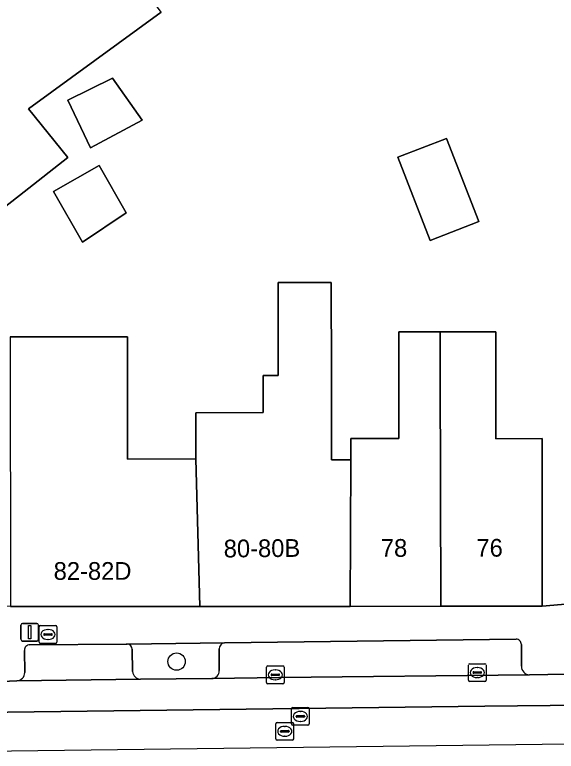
# Model space of a CAD drawing. Extents: x 159716 to 160783, y 383290 to 384031.
# Drawn here: x 159999.48 to 160030, y 383289.88 to 383331.4 of the extents above; entities that cross this region are included whole.
import ezdxf

# ---------------------------------------------------------------- set-up
doc = ezdxf.new("R2010")
doc.units = 0
for name, color, linetype in [('IMGEO_Boom', 7, 'Continuous'), ('IMGEO_Brandkraan', 7, 'Continuous'), ('IMGEO_Erf', 7, 'Continuous'), ('IMGEO_Groenvoorziening', 7, 'Continuous'), ('IMGEO_Kolk', 7, 'Continuous'), ('IMGEO_Lichtmast', 7, 'Continuous'), ('IMGEO_Pand', 7, 'Continuous'), ('IMGEO_Pand_nummerreeks', 7, 'Continuous'), ('IMGEO_Parkeervlak_open', 7, 'Continuous'), ('IMGEO_Rijbaan_lokaal_gesloten', 7, 'Continuous'), ('IMGEO_Rijbaan_lokaal_open', 7, 'Continuous'), ('IMGEO_Rioolput', 7, 'Continuous'), ('IMGEO_Voetpad_open', 7, 'Continuous')]:
    doc.layers.add(name, color=color, linetype=linetype)

msp = doc.modelspace()

# ---------------------------------------------------------------- linework, layer by layer
at = {"layer": 'IMGEO_Boom'}
msp.add_circle((160008.6, 383294.941), 0.489, dxfattribs=at)
at = {"layer": 'IMGEO_Brandkraan'}
for p, q in [((160000.852, 383296.043), (160000.852, 383296.895)), ((160000.927, 383296.969), (160001.779, 383296.969)), ((160001.34, 383296.749), (160001.365, 383296.749)), ((160001.853, 383296.895), (160001.853, 383296.043)), ((160001.111, 383296.463), (160001.111, 383296.475)), ((160001.549, 383296.426), (160001.151, 383296.426)), ((160001.154, 383296.512), (160001.552, 383296.512)), ((160001.595, 383296.475), (160001.595, 383296.463)), ((160001.779, 383295.969), (160000.927, 383295.969)), ((160001.363, 383296.189), (160001.338, 383296.189))]:
    msp.add_line(p, q, dxfattribs=at)
for points in [[(160000.852, 383296.043), (160000.852, 383296.895)], [(160000.927, 383296.969), (160001.779, 383296.969)], [(160001.853, 383296.895), (160001.853, 383296.043)], [(160001.779, 383295.969), (160000.927, 383295.969)]]:
    msp.add_lwpolyline(points, dxfattribs=at)
for centre, radius, start, end in [((160000.929, 383296.893), 0.0765, 91.552, 178.448), ((160000.929, 383296.893), 0.0765, 91.552, 178.448), ((160001.777, 383296.893), 0.0765, 1.552, 88.448), ((160001.777, 383296.893), 0.0765, 1.552, 88.448), ((160001.151, 383296.472), 0.0403, 85.8775, 175.7526), ((160001.148, 383296.462), 0.0366, 178.938, 274.7102), ((160001.552, 383296.469), 0.043, 264.8664, 352.4533), ((160001.556, 383296.474), 0.0386, 1.7309, 96.639), ((160000.929, 383296.045), 0.0765, 181.552, 268.448), ((160000.929, 383296.045), 0.0765, 181.552, 268.448), ((160001.777, 383296.045), 0.0765, 271.552, 358.448), ((160001.777, 383296.045), 0.0765, 271.552, 358.448)]:
    msp.add_arc(centre, radius, start, end, dxfattribs=at)
for centre, major_axis, ratio, start_param, end_param in [((160001.339, 383296.469), (-0.387, 0.002), 0.722429, 4.712389, 7.853982), ((160001.364, 383296.469), (-0.39, 0.002), 0.717154, 1.570796, 4.712389)]:
    msp.add_ellipse(centre, major_axis=major_axis, ratio=ratio, start_param=start_param, end_param=end_param, dxfattribs=at)
at = {"layer": 'IMGEO_Erf'}
for points in [[(160007.736, 383331.548), (160000.251, 383326.099), (160002.477, 383323.348), (160000, 383321.412), (159989.169, 383312.946), (159985.228, 383309.868), (159986.866, 383307.586)], [(159999.223, 383313.243), (160005.829, 383313.244), (160005.837, 383306.359), (160009.683, 383306.364), (160009.68, 383308.972), (160013.483, 383308.976), (160013.48, 383311.06), (160014.323, 383311.061), (160014.317, 383316.311), (160017.318, 383316.315), (160017.325, 383311.064), (160017.331, 383306.308), (160018.412, 383306.309), (160018.411, 383307.51), (160021.128, 383307.514), (160021.124, 383311.387), (160021.122, 383313.526), (160023.458, 383313.529), (160026.586, 383313.532), (160026.588, 383311.394), (160026.593, 383307.503), (160029.195, 383307.507), (160029.205, 383298.058), (160051.807, 383300.026)]]:
    msp.add_lwpolyline(points, dxfattribs=at)
for points in [[(160006.667, 383325.468), (160003.756, 383323.899), (160002.463, 383326.581), (160004.981, 383327.826)], [(160025.64, 383319.74), (160022.893, 383318.672), (160021.068, 383323.366), (160023.815, 383324.434)], [(160005.754, 383320.23), (160003.297, 383318.582), (160001.665, 383321.437), (160004.228, 383322.901)]]:
    msp.add_lwpolyline(points, close=True, dxfattribs=at)
at = {"layer": 'IMGEO_Groenvoorziening'}
for points in [[(160011.293, 383295.996), (160005.822, 383295.928)], [(160006.089, 383295.635), (160006.118, 383294.381)], [(160011.004, 383294.436), (160011.007, 383295.654)], [(160006.567, 383293.953), (160010.577, 383293.982)]]:
    msp.add_lwpolyline(points, dxfattribs=at)
for centre, radius, start, end in [((160005.798, 383295.638), 0.291, 359.4128, 85.2707), ((160011.345, 383295.662), 0.339, 98.9183, 181.2731), ((160006.571, 383294.406), 0.453, 183.1957, 269.5477), ((160010.558, 383294.427), 0.446, 272.4144, 1.0963)]:
    msp.add_arc(centre, radius, start, end, dxfattribs=at)
at = {"layer": 'IMGEO_Kolk'}
for p, q in [((160013.737, 383294.692), (160014.589, 383294.692)), ((160025.044, 383293.896), (160025.044, 383294.748)), ((160025.119, 383294.822), (160025.971, 383294.822)), ((160026.045, 383294.748), (160026.045, 383293.896)), ((160013.662, 383293.766), (160013.662, 383294.618)), ((160013.964, 383294.235), (160014.362, 383294.235)), ((160014.15, 383294.472), (160014.175, 383294.472)), ((160014.663, 383294.618), (160014.663, 383293.766)), ((160025.303, 383294.316), (160025.303, 383294.328)), ((160025.741, 383294.279), (160025.343, 383294.279)), ((160025.346, 383294.365), (160025.744, 383294.365)), ((160025.532, 383294.602), (160025.557, 383294.602)), ((160025.787, 383294.328), (160025.787, 383294.316)), ((160013.921, 383294.186), (160013.921, 383294.198)), ((160014.359, 383294.149), (160013.961, 383294.149)), ((160014.173, 383293.912), (160014.148, 383293.912)), ((160014.405, 383294.198), (160014.405, 383294.186)), ((160025.971, 383293.822), (160025.119, 383293.822)), ((160025.555, 383294.042), (160025.53, 383294.042)), ((160014.589, 383293.692), (160013.737, 383293.692))]:
    msp.add_line(p, q, dxfattribs=at)
for points in [[(160013.737, 383294.692), (160014.589, 383294.692)], [(160025.044, 383293.896), (160025.044, 383294.748)], [(160025.119, 383294.822), (160025.971, 383294.822)], [(160026.045, 383294.748), (160026.045, 383293.896)], [(160013.662, 383293.766), (160013.662, 383294.618)], [(160014.663, 383294.618), (160014.663, 383293.766)], [(160025.971, 383293.822), (160025.119, 383293.822)], [(160014.589, 383293.692), (160013.737, 383293.692)]]:
    msp.add_lwpolyline(points, dxfattribs=at)
for centre, radius, start, end in [((160013.739, 383294.616), 0.0765, 91.552, 178.448), ((160013.739, 383294.616), 0.0765, 91.552, 178.448), ((160014.587, 383294.616), 0.0765, 1.552, 88.448), ((160014.587, 383294.616), 0.0765, 1.552, 88.448), ((160025.121, 383294.746), 0.0765, 91.552, 178.448), ((160025.121, 383294.746), 0.0765, 91.552, 178.448), ((160025.969, 383294.746), 0.0765, 1.552, 88.448), ((160025.969, 383294.746), 0.0765, 1.552, 88.448), ((160013.961, 383294.195), 0.0403, 85.8775, 175.7526), ((160014.366, 383294.197), 0.0386, 1.7309, 96.639), ((160025.343, 383294.325), 0.0403, 85.8775, 175.7526), ((160025.34, 383294.315), 0.0366, 178.938, 274.7102), ((160025.744, 383294.322), 0.043, 264.8664, 352.4533), ((160025.748, 383294.327), 0.0386, 1.7309, 96.639), ((160013.958, 383294.185), 0.0366, 178.938, 274.7102), ((160014.362, 383294.192), 0.043, 264.8664, 352.4533), ((160025.121, 383293.898), 0.0765, 181.552, 268.448), ((160025.121, 383293.898), 0.0765, 181.552, 268.448), ((160025.969, 383293.898), 0.0765, 271.552, 358.448), ((160025.969, 383293.898), 0.0765, 271.552, 358.448), ((160013.739, 383293.768), 0.0765, 181.552, 268.448), ((160013.739, 383293.768), 0.0765, 181.552, 268.448), ((160014.587, 383293.768), 0.0765, 271.552, 358.448), ((160014.587, 383293.768), 0.0765, 271.552, 358.448)]:
    msp.add_arc(centre, radius, start, end, dxfattribs=at)
for centre, major_axis, ratio, start_param, end_param in [((160014.149, 383294.192), (-0.387, 0.002), 0.722429, 4.712389, 7.853982), ((160014.174, 383294.192), (-0.39, 0.002), 0.717154, 1.570796, 4.712389), ((160025.531, 383294.322), (-0.387, 0.002), 0.722429, 4.712389, 7.853982), ((160025.556, 383294.322), (-0.39, 0.002), 0.717154, 1.570796, 4.712389)]:
    msp.add_ellipse(centre, major_axis=major_axis, ratio=ratio, start_param=start_param, end_param=end_param, dxfattribs=at)
at = {"layer": 'IMGEO_Lichtmast'}
for p, q in [((159999.823, 383296.196), (159999.823, 383296.996)), ((159999.823, 383296.996), (159999.823, 383296.196)), ((159999.923, 383297.096), (160000.713, 383297.096)), ((160000.713, 383297.096), (159999.923, 383297.096)), ((160000.813, 383296.996), (160000.813, 383296.196)), ((160000.813, 383296.196), (160000.813, 383296.996)), ((160000.713, 383296.096), (159999.923, 383296.096)), ((159999.923, 383296.096), (160000.713, 383296.096))]:
    msp.add_line(p, q, dxfattribs=at)
msp.add_lwpolyline([(160000.243, 383296.971), (160000.393, 383296.971), (160000.393, 383296.221), (160000.243, 383296.221), (160000.243, 383296.971)], dxfattribs=at)
for centre, start, end in [((159999.923, 383296.996), 90, 180), ((159999.923, 383296.996), 90, 180), ((160000.713, 383296.996), 0, 90), ((160000.713, 383296.996), 360, 90), ((159999.923, 383296.196), 180, 270), ((159999.923, 383296.196), 180, 270), ((160000.713, 383296.196), 270, 0), ((160000.713, 383296.196), 270, 0)]:
    msp.add_arc(centre, 0.1, start, end, dxfattribs=at)
at = {"layer": 'IMGEO_Pand'}
for points in [[(160000, 383321.412), (160002.477, 383323.348), (160000.251, 383326.099), (160007.736, 383331.548), (160002.683, 383338.49), (159994.989, 383332.888), (159993.871, 383331.942), (159980.078, 383320.999), (159985.228, 383309.868), (159989.169, 383312.946)], [(160002.463, 383326.581), (160003.756, 383323.899), (160006.667, 383325.468), (160004.981, 383327.826)], [(160025.64, 383319.74), (160023.815, 383324.434), (160021.068, 383323.366), (160022.893, 383318.672)], [(160004.228, 383322.901), (160001.665, 383321.437), (160003.297, 383318.582), (160005.754, 383320.23)], [(160018.39, 383298.054), (160018.412, 383306.309), (160017.331, 383306.308), (160017.325, 383311.064), (160017.318, 383316.315), (160014.317, 383316.311), (160014.323, 383311.061), (160013.48, 383311.06), (160013.483, 383308.976), (160009.68, 383308.972), (160009.683, 383306.364), (160009.914, 383298.051)], [(160018.39, 383298.054), (160023.487, 383298.056), (160023.461, 383311.39), (160023.458, 383313.529), (160021.122, 383313.526), (160021.124, 383311.387), (160021.128, 383307.514), (160018.411, 383307.51), (160018.412, 383306.309)], [(160023.458, 383313.529), (160023.461, 383311.39), (160023.487, 383298.056), (160029.205, 383298.058), (160029.195, 383307.507), (160026.593, 383307.503), (160026.588, 383311.394), (160026.586, 383313.532)], [(160009.683, 383306.364), (160005.837, 383306.359), (160005.829, 383313.244), (159999.223, 383313.243), (159999.241, 383298.046), (160000, 383298.047), (160009.914, 383298.051)]]:
    msp.add_lwpolyline(points, close=True, dxfattribs=at)
at = {"layer": 'IMGEO_Parkeervlak_open'}
for points in [[(160005.822, 383295.928), (160005.765, 383295.928), (160000.325, 383295.889)], [(160027.732, 383296.209), (160011.293, 383295.996)], [(160028.033, 383294.681), (160028.029, 383295.897)], [(160000.031, 383295.57), (160000.04, 383294.322)], [(160006.118, 383294.381), (160006.089, 383295.635)], [(160011.007, 383295.654), (160011.004, 383294.436)], [(159999.6, 383293.851), (160006.567, 383293.953)], [(160010.577, 383293.982), (160014.409, 383294.041), (160028.488, 383294.189)]]:
    msp.add_lwpolyline(points, dxfattribs=at)
for centre, radius, start, end in [((160005.798, 383295.638), 0.291, 359.4128, 85.2707), ((160011.345, 383295.662), 0.339, 98.9183, 181.2731), ((160027.725, 383295.905), 0.304, 358.4744, 88.7038), ((160000.317, 383295.602), 0.288, 88.3807, 186.2901), ((160028.511, 383294.667), 0.478, 178.3074, 267.2177), ((159999.556, 383294.333), 0.485, 275.2554, 358.6425), ((160006.571, 383294.406), 0.453, 183.1957, 269.5477), ((160010.558, 383294.427), 0.446, 272.4144, 1.0963)]:
    msp.add_arc(centre, radius, start, end, dxfattribs=at)
at = {"layer": 'IMGEO_Rijbaan_lokaal_gesloten'}
msp.add_lwpolyline([(160150.106, 383295.703), (160091.491, 383295.018), (160080.943, 383294.873), (160059.499, 383294.598), (160047.505, 383294.448), (160047.439, 383294.447), (160040.647, 383294.363), (160034.154, 383294.287), (160032.6, 383294.278), (160028.488, 383294.189), (160014.409, 383294.041), (160010.577, 383293.982), (160006.567, 383293.953), (159999.6, 383293.851), (159995.123, 383293.652), (159995.296, 383291.929), (159997.559, 383292.063), (160025.97, 383292.419), (160040.677, 383292.583), (160047.427, 383292.731), (160059.219, 383292.845), (160080.212, 383293.115), (160098.531, 383293.352), (160124.008, 383293.611)], dxfattribs=at)
at = {"layer": 'IMGEO_Rijbaan_lokaal_open'}
msp.add_lwpolyline([(160059.246, 383291.123), (160059.219, 383292.845), (160047.427, 383292.731), (160040.677, 383292.583), (160025.97, 383292.419), (159997.559, 383292.063), (159997.778, 383289.885), (160035.187, 383290.367), (160050.172, 383290.838)], close=True, dxfattribs=at)
at = {"layer": 'IMGEO_Rioolput'}
for p, q in [((160015.077, 383291.425), (160015.077, 383292.277)), ((160015.152, 383292.351), (160016.004, 383292.351)), ((160016.078, 383292.277), (160016.078, 383291.425)), ((160015.336, 383291.845), (160015.336, 383291.857)), ((160015.774, 383291.808), (160015.376, 383291.808)), ((160015.379, 383291.894), (160015.777, 383291.894)), ((160015.565, 383292.131), (160015.59, 383292.131)), ((160015.82, 383291.857), (160015.82, 383291.845)), ((160014.196, 383290.584), (160014.196, 383291.436)), ((160014.271, 383291.51), (160015.123, 383291.51)), ((160016.004, 383291.351), (160015.152, 383291.351)), ((160015.197, 383291.436), (160015.197, 383290.584)), ((160015.588, 383291.571), (160015.563, 383291.571)), ((160014.455, 383291.004), (160014.455, 383291.016)), ((160014.893, 383290.967), (160014.495, 383290.967)), ((160014.498, 383291.053), (160014.896, 383291.053)), ((160014.684, 383291.29), (160014.709, 383291.29)), ((160014.939, 383291.016), (160014.939, 383291.004)), ((160015.123, 383290.51), (160014.271, 383290.51)), ((160014.707, 383290.73), (160014.682, 383290.73))]:
    msp.add_line(p, q, dxfattribs=at)
for points in [[(160015.077, 383291.425), (160015.077, 383292.277)], [(160015.152, 383292.351), (160016.004, 383292.351)], [(160016.078, 383292.277), (160016.078, 383291.425)], [(160014.196, 383290.584), (160014.196, 383291.436)], [(160014.271, 383291.51), (160015.123, 383291.51)], [(160016.004, 383291.351), (160015.152, 383291.351)], [(160015.197, 383291.436), (160015.197, 383290.584)], [(160015.123, 383290.51), (160014.271, 383290.51)]]:
    msp.add_lwpolyline(points, dxfattribs=at)
for centre, radius, start, end in [((160015.154, 383292.275), 0.0765, 91.552, 178.448), ((160015.154, 383292.275), 0.0765, 91.552, 178.448), ((160016.002, 383292.275), 0.0765, 1.552, 88.448), ((160016.002, 383292.275), 0.0765, 1.552, 88.448), ((160015.376, 383291.854), 0.0403, 85.8775, 175.7526), ((160015.373, 383291.844), 0.0366, 178.938, 274.7102), ((160015.777, 383291.851), 0.043, 264.8664, 352.4533), ((160015.781, 383291.856), 0.0386, 1.7309, 96.639), ((160014.273, 383291.434), 0.0765, 91.552, 178.448), ((160014.273, 383291.434), 0.0765, 91.552, 178.448), ((160015.154, 383291.427), 0.0765, 181.552, 268.448), ((160015.154, 383291.427), 0.0765, 181.552, 268.448), ((160015.121, 383291.434), 0.0765, 1.552, 88.448), ((160015.121, 383291.434), 0.0765, 1.552, 88.448), ((160016.002, 383291.427), 0.0765, 271.552, 358.448), ((160016.002, 383291.427), 0.0765, 271.552, 358.448), ((160014.495, 383291.013), 0.0403, 85.8775, 175.7526), ((160014.492, 383291.003), 0.0366, 178.938, 274.7102), ((160014.896, 383291.01), 0.043, 264.8664, 352.4533), ((160014.9, 383291.015), 0.0386, 1.7309, 96.639), ((160014.273, 383290.586), 0.0765, 181.552, 268.448), ((160014.273, 383290.586), 0.0765, 181.552, 268.448), ((160015.121, 383290.586), 0.0765, 271.552, 358.448), ((160015.121, 383290.586), 0.0765, 271.552, 358.448)]:
    msp.add_arc(centre, radius, start, end, dxfattribs=at)
for centre, major_axis, ratio, start_param, end_param in [((160015.564, 383291.851), (-0.387, 0.002), 0.722429, 4.712389, 7.853982), ((160015.589, 383291.851), (-0.39, 0.002), 0.717154, 1.570796, 4.712389), ((160014.683, 383291.01), (-0.387, 0.002), 0.722429, 4.712389, 7.853982), ((160014.708, 383291.01), (-0.39, 0.002), 0.717154, 1.570796, 4.712389)]:
    msp.add_ellipse(centre, major_axis=major_axis, ratio=ratio, start_param=start_param, end_param=end_param, dxfattribs=at)
at = {"layer": 'IMGEO_Voetpad_open'}
for points in [[(160051.807, 383300.026), (160029.205, 383298.058), (160023.487, 383298.056), (160018.39, 383298.054), (160009.914, 383298.051), (160000, 383298.047), (159999.241, 383298.046), (159996.044, 383298.242), (159987.343, 383299.335), (159988.857, 383296.402)], [(160028.488, 383294.189), (160032.6, 383294.278), (160032.555, 383296.297), (160034.859, 383296.271), (160040.872, 383296.344), (160046.739, 383296.432)], [(160000.325, 383295.889), (160005.765, 383295.928), (160005.822, 383295.928), (160011.293, 383295.996), (160027.732, 383296.209)], [(160028.029, 383295.897), (160028.033, 383294.681)], [(160000.04, 383294.322), (160000.031, 383295.57)], [(159994.139, 383293.566), (159995.123, 383293.652), (159999.6, 383293.851)]]:
    msp.add_lwpolyline(points, dxfattribs=at)
for centre, radius, start, end in [((160027.725, 383295.905), 0.304, 358.4744, 88.7038), ((160000.317, 383295.602), 0.288, 88.3807, 186.2901), ((160028.511, 383294.667), 0.478, 178.3074, 267.2177), ((159999.556, 383294.333), 0.485, 275.2554, 358.6425)]:
    msp.add_arc(centre, radius, start, end, dxfattribs=at)

# ---------------------------------------------------------------- texts
at = {"layer": 'IMGEO_Pand_nummerreeks'}
for s, rotation, p in [('80-80B', 0.514, (160011.259, 383300.809)), ('78', 0.0982, (160020.111, 383300.845)), ('76', 0.0982, (160025.497, 383300.854)), ('82-82D', 0.0229, (160001.67, 383299.548))]:
    msp.add_text(s, height=1, rotation=rotation, dxfattribs=at).set_placement(p)

doc.saveas('drawing.dxf')
